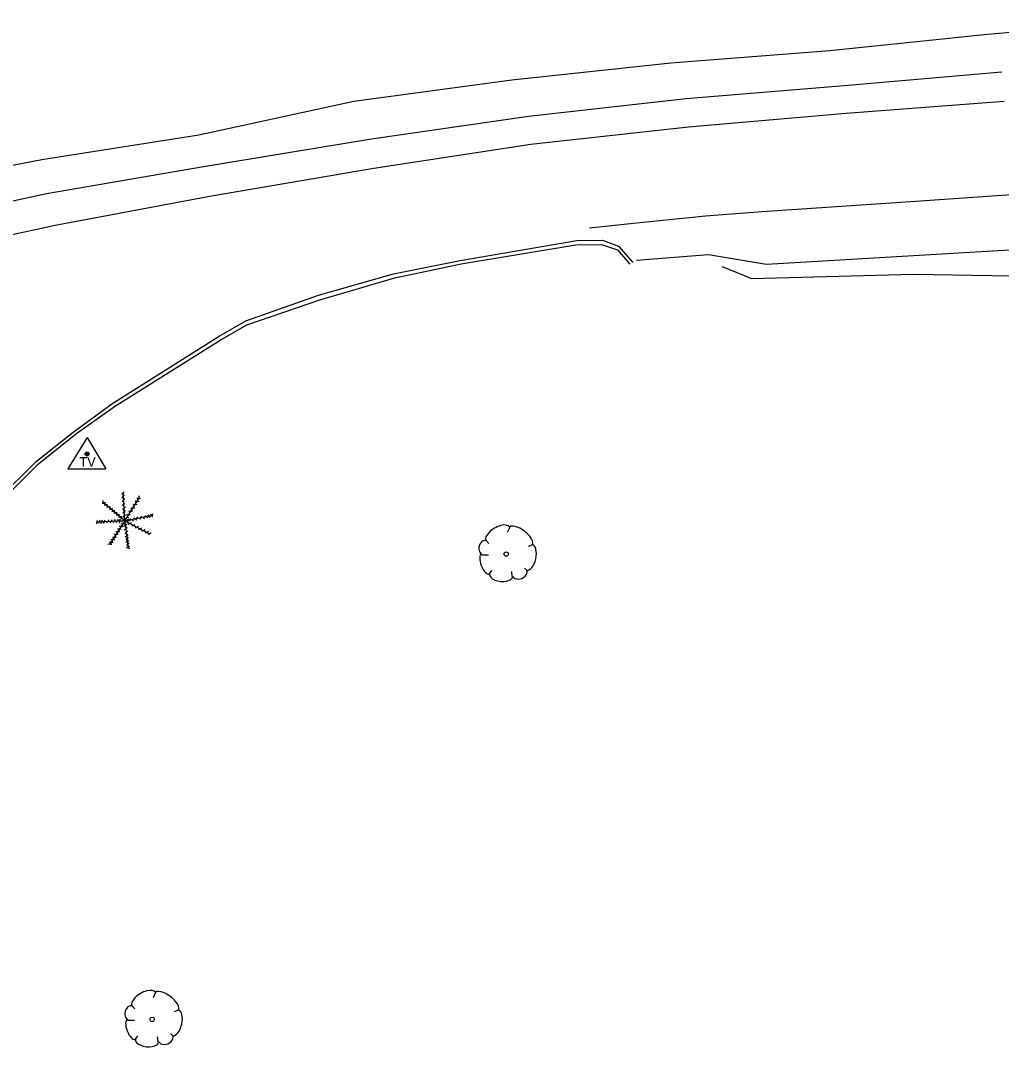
# Model space of a CAD drawing. Extents: x 1042086 to 1119166, y 1916606 to 1927565.
# Drawn here: x 1043670.3 to 1043824.9, y 1926368.2 to 1926530.1 of the extents above; entities that cross this region are included whole.
import ezdxf

# ---------------------------------------------------------------- set-up
doc = ezdxf.new("R2010")
doc.units = 0
for name, color, linetype in [('S_CURB', 7, 'Continuous'), ('S_EDGE_PAVEMENT', 7, 'Continuous'), ('S_GRAVEL_ROAD', 7, 'Continuous'), ('S_SECONDARY_CTL', 7, 'Continuous'), ('S_SHOULDER', 7, 'Continuous'), ('S_TREE', 7, 'Continuous')]:
    doc.layers.add(name, color=color, linetype=linetype)

msp = doc.modelspace()

# ---------------------------------------------------------------- linework, layer by layer
at = {"layer": 'S_CURB'}
msp.add_lwpolyline([(1043610.23, 1926393.39), (1043627.29, 1926411.68), (1043644.37, 1926429.95), (1043661.48, 1926448.18), (1043667.22, 1926454.29), (1043673.15, 1926460.19), (1043678.95, 1926464.87), (1043685.12, 1926469.27), (1043701.79, 1926479.7), (1043705.97, 1926482.16), (1043717.49, 1926486.05), (1043729.28, 1926489.55), (1043739.73, 1926491.73), (1043757.83, 1926494.76), (1043761.87, 1926494.82), (1043764.41, 1926493.95), (1043766.32, 1926491.72)], dxfattribs=at)
at = {"layer": 'S_EDGE_PAVEMENT'}
for points in [[(1043379.57, 1926373.44), (1043398.5, 1926384.17), (1043420, 1926396.38), (1043441.71, 1926408.76), (1043463.61, 1926420.83), (1043485.65, 1926432.64), (1043507.89, 1926444.1), (1043530.61, 1926454.72), (1043555.31, 1926464.5), (1043578.92, 1926472.93), (1043602.85, 1926480.19), (1043626.98, 1926486.7), (1043651.29, 1926492.56), (1043675.75, 1926497.87), (1043700.4, 1926502.47), (1043725.97, 1926506.82), (1043750.72, 1926510.63), (1043775.56, 1926513.38), (1043800.45, 1926515.5), (1043825.35, 1926517.42)], [(1043759.98, 1926497.44), (1043766.93, 1926498.16), (1043778.25, 1926499.31), (1043787.22, 1926499.99), (1043812.14, 1926501.71), (1043837.06, 1926503.43)], [(1043609.64, 1926393.97), (1043626.9, 1926412.07), (1043643.95, 1926430.36), (1043661.07, 1926448.6), (1043666.8, 1926454.7), (1043672.75, 1926460.59), (1043678.6, 1926465.22), (1043684.68, 1926469.7), (1043701.6, 1926480.37), (1043705.8, 1926482.75), (1043717.27, 1926486.82), (1043729.1, 1926490.2), (1043739.57, 1926492.3), (1043757.97, 1926495.43), (1043762.01, 1926495.48), (1043764.53, 1926494.55), (1043766.79, 1926491.94)]]:
    msp.add_lwpolyline(points, dxfattribs=at)
at = {"layer": 'S_GRAVEL_ROAD'}
msp.add_lwpolyline([(1043780.9, 1926491.31), (1043785.51, 1926489.45), (1043811.02, 1926490.12), (1043829.52, 1926489.79)], dxfattribs=at)
at = {"layer": 'S_SECONDARY_CTL'}
for p, q in [((1043680.79, 1926464.39), (1043677.78, 1926459.44)), ((1043680.79, 1926464.39), (1043683.73, 1926459.44)), ((1043677.78, 1926459.44), (1043683.73, 1926459.44))]:
    msp.add_line(p, q, dxfattribs=at)
for radius in [0.311, 0.183, 0.103]:
    msp.add_circle((1043680.79, 1926461.78), radius, dxfattribs=at)
at = {"layer": 'S_SHOULDER'}
for points in [[(1043402.36, 1926392.24), (1043407.92, 1926402.12), (1043429.15, 1926414.97), (1043451.05, 1926427.55), (1043473.82, 1926437.97), (1043496.21, 1926449.43), (1043519.25, 1926459.61), (1043542.18, 1926470.11), (1043552.41, 1926474.93), (1043576.1, 1926483.66), (1043600.3, 1926490.55), (1043624.54, 1926496.95), (1043648.88, 1926503.43), (1043673.68, 1926508.19), (1043698.4, 1926512.07), (1043722.85, 1926517.42), (1043747.76, 1926520.78), (1043772.79, 1926523.47), (1043797.88, 1926525.4), (1043822.72, 1926527.97), (1043847.76, 1926530.12)], [(1043395.57, 1926384.91), (1043395.9, 1926386.78), (1043396.52, 1926387.84), (1043417.95, 1926399.94), (1043439.4, 1926412.79), (1043461.3, 1926424.84), (1043483.14, 1926437), (1043505.37, 1926448.49), (1043528.05, 1926459.19), (1043553.89, 1926469.75), (1043577.59, 1926477.85), (1043601.56, 1926484.96), (1043625.72, 1926491.38), (1043649.95, 1926497.52), (1043674.4, 1926502.86), (1043699.15, 1926507.09), (1043725.6, 1926511.48), (1043750.38, 1926515.02), (1043775.21, 1926517.81), (1043800.11, 1926519.87), (1043824.99, 1926522.01)], [(1043767.38, 1926492.34), (1043778.73, 1926493.23), (1043787.87, 1926491.7), (1043812.81, 1926493.15), (1043837.74, 1926494.64)]]:
    msp.add_lwpolyline(points, dxfattribs=at)
at = {"layer": 'S_TREE'}
for p, q in [((1043686.48, 1926455.32), (1043686.25, 1926455.52)), ((1043686.51, 1926454.76), (1043686.28, 1926454.96)), ((1043686.73, 1926451.24), (1043686.46, 1926455.68)), ((1043686.47, 1926455.57), (1043686.66, 1926455.8)), ((1043686.5, 1926455.09), (1043686.69, 1926455.33)), ((1043686.53, 1926454.49), (1043686.72, 1926454.73)), ((1043686.73, 1926451.24), (1043689.07, 1926454.93)), ((1043688.8, 1926454.55), (1043688.71, 1926454.84)), ((1043688.94, 1926454.71), (1043689.23, 1926454.76)), ((1043689.05, 1926454.89), (1043688.96, 1926455.18)), ((1043683.45, 1926453.98), (1043683.15, 1926453.94)), ((1043686.73, 1926451.24), (1043683.27, 1926454.15)), ((1043683.31, 1926454.13), (1043683.31, 1926454.43)), ((1043683.8, 1926453.71), (1043683.5, 1926453.68)), ((1043683.62, 1926453.88), (1043683.62, 1926454.18)), ((1043684.16, 1926453.38), (1043683.86, 1926453.36)), ((1043683.98, 1926453.58), (1043683.98, 1926453.88)), ((1043684.39, 1926453.22), (1043684.39, 1926453.52)), ((1043684.8, 1926452.89), (1043684.8, 1926453.19)), ((1043686.54, 1926454.18), (1043686.31, 1926454.38)), ((1043686.56, 1926453.53), (1043686.34, 1926453.73)), ((1043686.6, 1926452.93), (1043686.38, 1926453.13)), ((1043686.57, 1926453.78), (1043686.76, 1926454.02)), ((1043686.64, 1926453.22), (1043686.83, 1926453.45)), ((1043687.83, 1926453.02), (1043687.75, 1926453.3)), ((1043688.05, 1926453.26), (1043688.34, 1926453.3)), ((1043688.21, 1926453.58), (1043688.12, 1926453.87)), ((1043688.37, 1926453.8), (1043688.67, 1926453.84)), ((1043688.51, 1926454.1), (1043688.42, 1926454.39)), ((1043688.69, 1926454.29), (1043688.99, 1926454.33)), ((1043684.62, 1926453.01), (1043684.32, 1926452.99)), ((1043684.98, 1926452.68), (1043684.68, 1926452.66)), ((1043685.31, 1926452.42), (1043685.01, 1926452.39)), ((1043685.12, 1926452.61), (1043685.12, 1926452.91)), ((1043685.65, 1926452.12), (1043685.36, 1926452.1)), ((1043685.49, 1926452.31), (1043685.49, 1926452.61)), ((1043686.02, 1926451.82), (1043685.72, 1926451.8)), ((1043685.86, 1926452), (1043685.86, 1926452.3)), ((1043686.07, 1926451.25), (1043685.91, 1926451.5)), ((1043686.38, 1926451.53), (1043686.08, 1926451.5)), ((1043686.22, 1926451.69), (1043686.22, 1926451.99)), ((1043686.64, 1926452.37), (1043686.42, 1926452.56)), ((1043686.65, 1926451.75), (1043686.43, 1926451.94)), ((1043686.65, 1926452.65), (1043686.84, 1926452.88)), ((1043686.68, 1926451.98), (1043686.87, 1926452.21)), ((1043686.73, 1926451.24), (1043691.15, 1926452.11)), ((1043687.08, 1926451.73), (1043687.38, 1926451.78)), ((1043687.18, 1926452), (1043687.09, 1926452.28)), ((1043687.11, 1926451.33), (1043687.31, 1926451.55)), ((1043687.36, 1926452.2), (1043687.66, 1926452.24)), ((1043687.54, 1926452.53), (1043687.45, 1926452.81)), ((1043687.51, 1926451.39), (1043687.71, 1926451.61)), ((1043687.7, 1926452.74), (1043688, 1926452.78)), ((1043688.04, 1926451.49), (1043688.24, 1926451.71)), ((1043688.38, 1926451.55), (1043688.64, 1926451.39)), ((1043688.6, 1926451.62), (1043688.81, 1926451.84)), ((1043688.99, 1926451.68), (1043689.24, 1926451.52)), ((1043689.24, 1926451.76), (1043689.44, 1926451.98)), ((1043689.57, 1926451.78), (1043689.82, 1926451.62)), ((1043689.83, 1926451.85), (1043690.03, 1926452.07)), ((1043690.08, 1926451.9), (1043690.33, 1926451.74)), ((1043690.31, 1926451.95), (1043690.52, 1926452.18)), ((1043690.51, 1926451.99), (1043690.76, 1926451.83)), ((1043690.76, 1926452.04), (1043690.96, 1926452.27)), ((1043690.91, 1926452.05), (1043691.17, 1926451.89)), ((1043690.99, 1926452.1), (1043691.19, 1926452.32)), ((1043682.36, 1926451.03), (1043682.23, 1926450.76)), ((1043686.73, 1926451.24), (1043682.28, 1926451.03)), ((1043682.51, 1926451.05), (1043682.34, 1926451.3)), ((1043682.71, 1926451.06), (1043682.58, 1926450.79)), ((1043682.9, 1926451.08), (1043682.73, 1926451.33)), ((1043683.05, 1926451.08), (1043682.92, 1926450.81)), ((1043683.3, 1926451.08), (1043683.13, 1926451.33)), ((1043683.47, 1926451.09), (1043683.34, 1926450.82)), ((1043683.7, 1926451.11), (1043683.53, 1926451.35)), ((1043683.98, 1926451.11), (1043683.85, 1926450.85)), ((1043684.27, 1926451.12), (1043684.1, 1926451.37)), ((1043686.73, 1926451.24), (1043684.35, 1926447.47)), ((1043684.54, 1926451.14), (1043684.41, 1926450.87)), ((1043684.82, 1926451.16), (1043684.65, 1926451.4)), ((1043685.03, 1926451.16), (1043684.89, 1926450.89)), ((1043685.3, 1926451.17), (1043685.13, 1926451.42)), ((1043685.5, 1926451.18), (1043685.37, 1926450.92)), ((1043685.74, 1926451.21), (1043685.57, 1926451.46)), ((1043685.89, 1926449.93), (1043685.59, 1926449.9)), ((1043685.96, 1926451.19), (1043685.82, 1926450.92)), ((1043686.16, 1926450.38), (1043685.87, 1926450.34)), ((1043686.03, 1926450.15), (1043686.11, 1926449.86)), ((1043686.4, 1926450.75), (1043686.1, 1926450.71)), ((1043686.34, 1926451.2), (1043686.21, 1926450.94)), ((1043686.31, 1926450.58), (1043686.39, 1926450.29)), ((1043686.53, 1926450.92), (1043686.6, 1926450.63)), ((1043686.79, 1926450.57), (1043686.6, 1926450.34)), ((1043686.86, 1926449.99), (1043686.66, 1926449.76)), ((1043686.73, 1926451.24), (1043690.65, 1926449.2)), ((1043686.73, 1926451.24), (1043687.26, 1926446.87)), ((1043686.81, 1926450.82), (1043687.07, 1926450.66)), ((1043686.85, 1926450.26), (1043687.1, 1926450.11)), ((1043687.06, 1926451.06), (1043687.33, 1926451.2)), ((1043687.24, 1926450.97), (1043687.31, 1926450.67)), ((1043687.35, 1926451.36), (1043687.6, 1926451.2)), ((1043687.54, 1926450.84), (1043687.8, 1926450.98)), ((1043687.82, 1926450.66), (1043687.89, 1926450.37)), ((1043687.87, 1926451.44), (1043688.12, 1926451.28)), ((1043688.09, 1926450.53), (1043688.36, 1926450.67)), ((1043688.36, 1926450.38), (1043688.43, 1926450.09)), ((1043688.65, 1926450.25), (1043688.91, 1926450.39)), ((1043688.88, 1926450.11), (1043688.95, 1926449.82)), ((1043689.13, 1926449.99), (1043689.4, 1926450.13)), ((1043747.41, 1926450.23), (1043747.02, 1926449.38)), ((1043684.83, 1926448.27), (1043684.54, 1926448.23)), ((1043685.07, 1926448.64), (1043684.78, 1926448.61)), ((1043684.99, 1926448.46), (1043685.07, 1926448.17)), ((1043685.37, 1926449.09), (1043685.07, 1926449.06)), ((1043685.23, 1926448.84), (1043685.31, 1926448.55)), ((1043685.63, 1926449.51), (1043685.34, 1926449.48)), ((1043685.52, 1926449.31), (1043685.59, 1926449.02)), ((1043685.78, 1926449.73), (1043685.85, 1926449.44)), ((1043686.94, 1926449.42), (1043686.75, 1926449.2)), ((1043687.01, 1926448.86), (1043686.82, 1926448.63)), ((1043687.08, 1926448.4), (1043686.88, 1926448.17)), ((1043686.93, 1926449.69), (1043687.19, 1926449.54)), ((1043687, 1926449.15), (1043687.25, 1926448.99)), ((1043687.07, 1926448.64), (1043687.32, 1926448.48)), ((1043689.42, 1926449.82), (1043689.49, 1926449.53)), ((1043689.67, 1926449.72), (1043689.93, 1926449.86)), ((1043689.93, 1926449.56), (1043690, 1926449.27)), ((1043690.22, 1926449.44), (1043690.48, 1926449.58)), ((1043690.42, 1926449.31), (1043690.49, 1926449.02)), ((1043690.61, 1926449.24), (1043690.87, 1926449.38)), ((1043684.38, 1926447.55), (1043684.08, 1926447.52)), ((1043684.58, 1926447.86), (1043684.28, 1926447.82)), ((1043684.51, 1926447.71), (1043684.58, 1926447.42)), ((1043684.73, 1926448.06), (1043684.81, 1926447.77)), ((1043687.12, 1926448.02), (1043686.92, 1926447.79)), ((1043687.17, 1926447.57), (1043686.98, 1926447.35)), ((1043687.22, 1926447.15), (1043687.02, 1926446.93)), ((1043687.1, 1926448.2), (1043687.36, 1926448.05)), ((1043687.14, 1926447.8), (1043687.4, 1926447.64)), ((1043687.21, 1926447.33), (1043687.47, 1926447.18)), ((1043687.25, 1926446.99), (1043687.5, 1926446.84)), ((1043743.61, 1926448.22), (1043744.11, 1926447.63)), ((1043750.97, 1926447.44), (1043750.31, 1926447.17)), ((1043742.95, 1926445.89), (1043744.08, 1926445.89)), ((1043744.11, 1926442.71), (1043744.58, 1926443.41)), ((1043750.2, 1926443.33), (1043749.73, 1926443.76)), ((1043747.8, 1926442.44), (1043747.72, 1926443.22)), ((1043691.6, 1926376.85), (1043691.22, 1926376)), ((1043687.81, 1926374.84), (1043688.31, 1926374.26)), ((1043695.17, 1926374.06), (1043694.51, 1926373.79)), ((1043687.15, 1926372.51), (1043688.27, 1926372.51)), ((1043688.31, 1926369.34), (1043688.78, 1926370.03)), ((1043691.99, 1926369.07), (1043691.91, 1926369.84)), ((1043694.39, 1926369.96), (1043693.93, 1926370.38))]:
    msp.add_line(p, q, dxfattribs=at)
for centre in [(1043746.85, 1926445.99), (1043691.05, 1926372.61)]:
    msp.add_circle(centre, 0.341, dxfattribs=at)
for centre, major_axis, ratio, start_param, end_param in [((1043745.51, 1926449.19), (1.86, 1.08), 0.471018, 0, 3.141593), ((1043749.17, 1926448.86), (-1.81, 1.36), 0.405113, 3.141593, 6.283186), ((1043743.28, 1926447.07), (0.31, 1.03), 0.646762, 0, 3.141593), ((1043750.52, 1926445.46), (0.46, 2.04), 0.482994, 3.141593, 6.283185), ((1043743.59, 1926444.42), (-0.61, 1.6), 0.420543, 6.283185, 9.424777), ((1043749, 1926442.93), (1.09, 0.46), 0.711534, 3.141592, 6.283185), ((1043746.05, 1926442.64), (-1.83, 0.19), 0.529943, 0, 3.141593), ((1043689.71, 1926375.81), (1.86, 1.08), 0.471018, 0, 3.141593), ((1043693.37, 1926375.49), (-1.81, 1.36), 0.405113, 3.141593, 6.283186), ((1043687.48, 1926373.7), (0.31, 1.03), 0.646762, 0, 3.141593), ((1043694.72, 1926372.08), (0.46, 2.04), 0.482994, 3.141593, 6.283185), ((1043687.78, 1926371.05), (-0.61, 1.6), 0.420543, 6.283185, 9.424777), ((1043690.24, 1926369.27), (-1.83, 0.19), 0.529943, 0, 3.141593), ((1043693.2, 1926369.56), (1.09, 0.46), 0.711534, 3.141592, 6.283185)]:
    msp.add_ellipse(centre, major_axis=major_axis, ratio=ratio, start_param=start_param, end_param=end_param, dxfattribs=at)

# ---------------------------------------------------------------- texts
at = {"layer": 'S_SECONDARY_CTL'}
msp.add_text('TV', height=1.5, rotation=360, dxfattribs=at).set_placement((1043679.58, 1926459.77))

doc.saveas('drawing.dxf')
